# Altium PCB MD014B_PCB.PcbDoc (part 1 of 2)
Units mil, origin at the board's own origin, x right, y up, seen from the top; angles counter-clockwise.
Board outline 2500 x 1545 mil, 2 copper layers (Top Layer, Bottom Layer), stack 64.8 mil thick; 63 components, 34 nets, 144 pads, 182 vias.
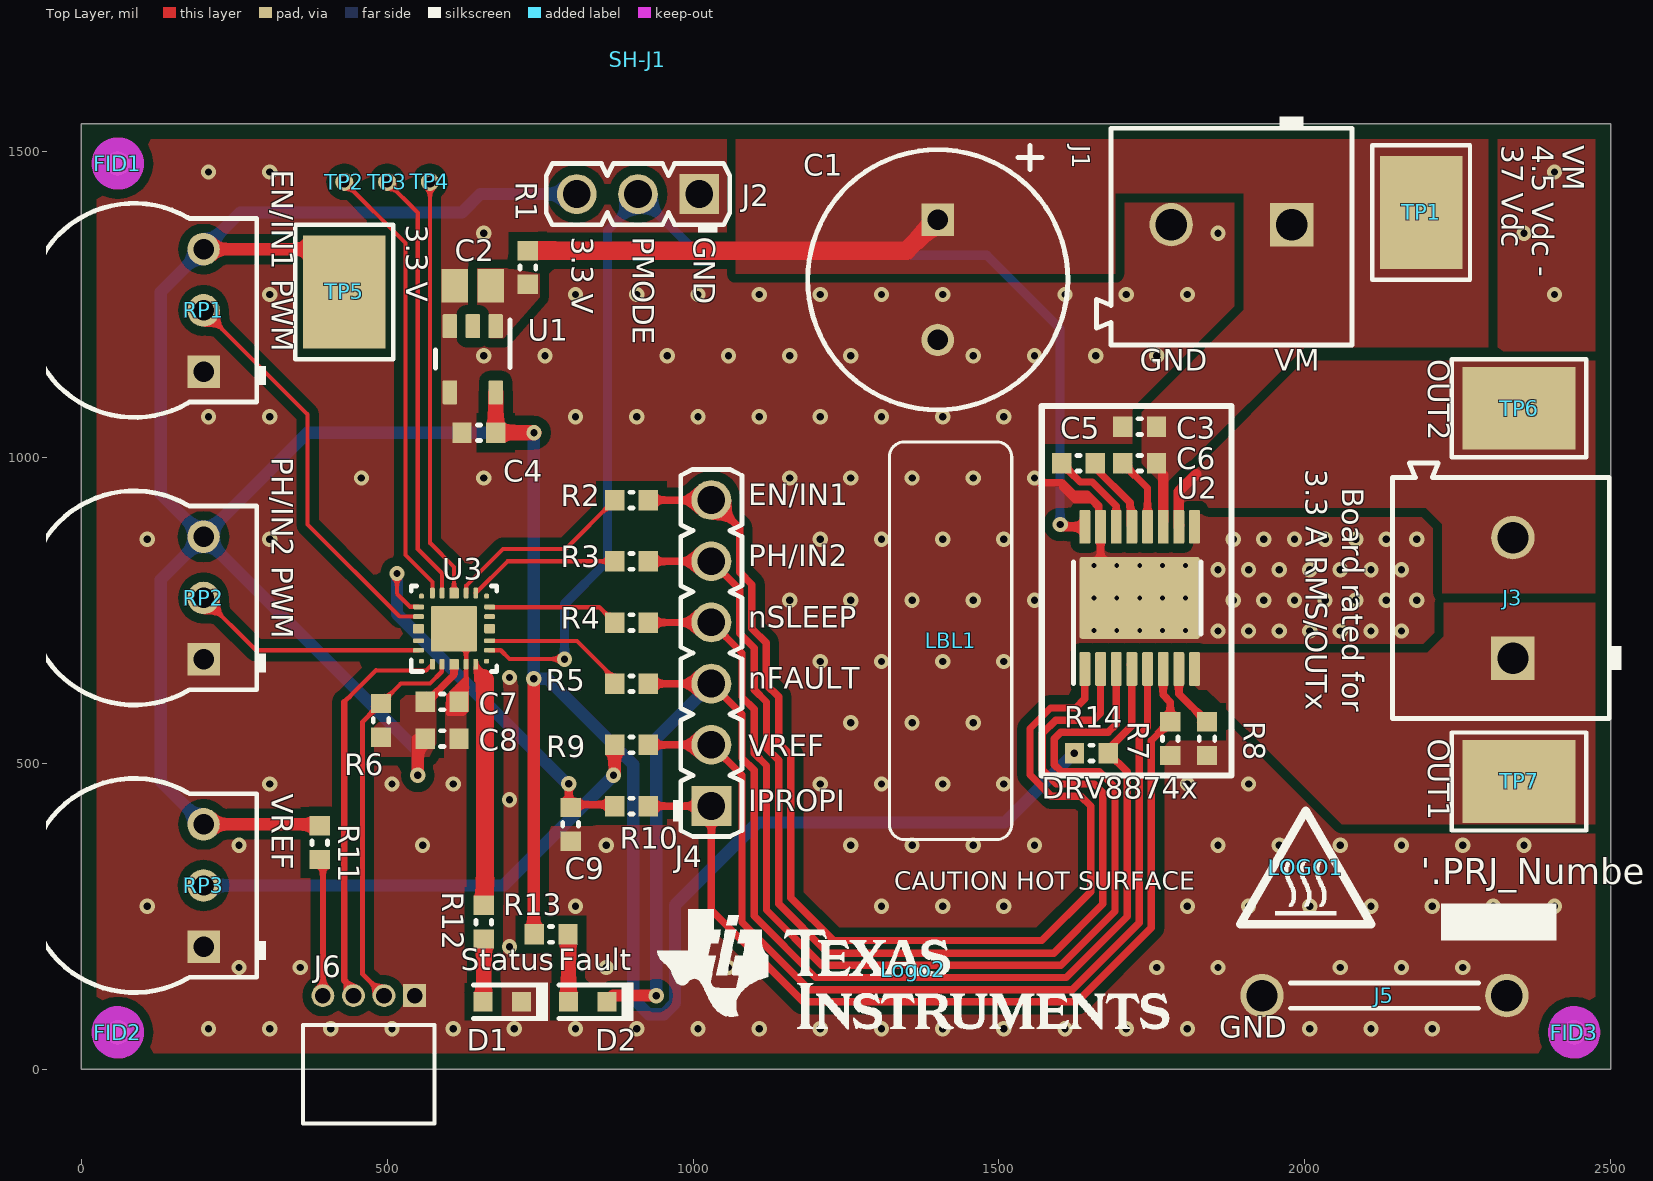
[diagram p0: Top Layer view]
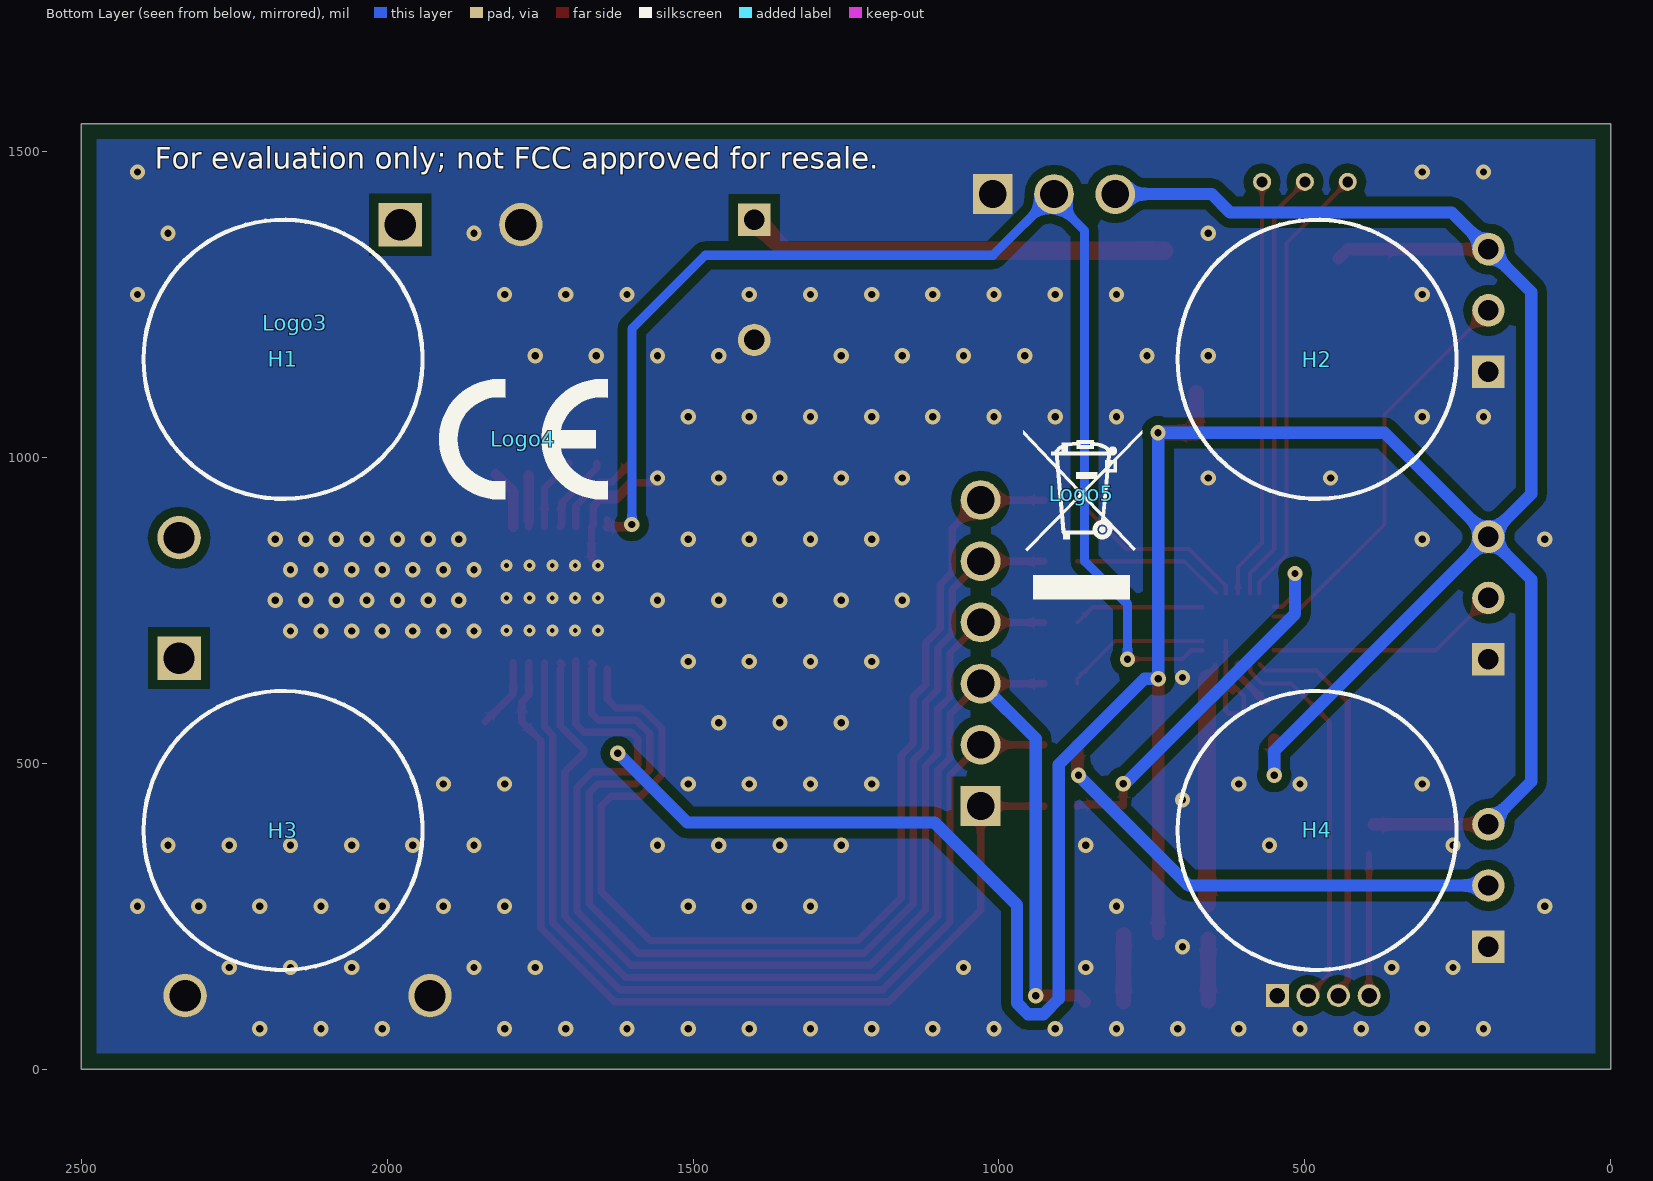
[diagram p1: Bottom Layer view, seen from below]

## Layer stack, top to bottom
Top Solder: solder mask 0.4, Solder Resist, Dk 3.5
Top Layer: signal copper 2.8
Dielectric1: core 59.2, FR-4, Dk 4.8
Bottom Layer: signal copper 2.8
Bottom Solder: solder mask 0.4, Solder Resist, Dk 3.5

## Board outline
0,0 2500,0 2500,1545 0,1545

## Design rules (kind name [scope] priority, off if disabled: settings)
AcuteAngle [All] p1: minimum=4.50000000000000E+0001 checktracksonly=FALSE
AssemblyTestPointUsage [All] p1: valid=2
BoardOutlineClearance BoardOutlineClearance_MountingHoles [OnCopper and InComponentClass('Mounting Holes')] p1: gap=40 ignorepadtopadclearanceinfootprint=FALSE
BoardOutlineClearance BoardOutlineClearance_Poly [OnCopper and IsPoly] p2: gap=25 ignorepadtopadclearanceinfootprint=FALSE
BoardOutlineClearance [OnCopper and Not InComponentClass('Logo') and not InComponentClass('FiducialMark') and not InRegion(1000,500,4000,800) and not InPoly] p3: gap=50 ignorepadtopadclearanceinfootprint=FALSE
Clearance "Stitching GND" [IsStitchingVia and InNet('GND') vs (IsVia and (Not IsStitchingVia)) Or IsPad] p1: gap=15 ignorepadtopadclearanceinfootprint=FALSE
Clearance Clearance_Keepouts [((IsTrack Or IsArc) And Not InPoly) And IsFree and IsKeepOut vs ((IsTrack Or IsArc) And Not InPoly) And IsFree and IsKeepOut] p2: gap=0 ignorepadtopadclearanceinfootprint=FALSE
Clearance Clearance_Poly [InPolygon] p3: gap=15 ignorepadtopadclearanceinfootprint=FALSE except(0: Arc-Hole Track-Hole SMDPad-Hole THPad-Hole Via-Hole Fill-Hole Poly-Hole Region-Hole Text-Hole)
Clearance Clearance_FiducialMark [IsKeepOut and InComponentClass('FiducialMark') vs IsPad and InComponentClass('FiducialMark')] p4: gap=0 ignorepadtopadclearanceinfootprint=FALSE
Clearance [All] p5: gap=7.87 ignorepadtopadclearanceinfootprint=FALSE except(0: Arc-Hole Track-Hole SMDPad-Hole THPad-Hole Via-Hole Fill-Hole Poly-Hole Region-Hole Text-Hole)
ComponentClearance ComponentClearance_MountingHoles_FiducialMarks [InComponentClass('Mounting Holes') vs InComponentClass('FiducialMark')] p1: gap=50 collisioncheckmode=3 verticalgap=10 showdistances=FALSE
ComponentClearance ComponentClearance_Shunt [InComponentClass('Header') vs InComponentClass('Shunt')] p2: gap=0 collisioncheckmode=3 verticalgap=0 showdistances=FALSE
ComponentClearance ComponentClearance_Logo [InComponentClass('Logo')] p3: gap=50 collisioncheckmode=3 verticalgap=10 showdistances=FALSE
ComponentClearance ComponentClearance_ScrewToNut [(HasFootprint('NY PMS 440 0025 PH')) vs (HasFootprint('Keystone_1902C'))] p4: gap=5 collisioncheckmode=3 verticalgap=10 showdistances=FALSE
ComponentClearance ComponentClearance_MountingHoles [InComponentClass('Mounting Holes')] p5: gap=250 collisioncheckmode=3 verticalgap=100000 showdistances=FALSE
ComponentClearance ComponentClearance_SmallPassives [HasFootprint('0201*') or HasFootprint('0402*') or HasFootprint('0508') or HasFootprint('0603*') or HasFootprint('0612') or HasFootprint('0805*') or HasFootprint('0815*') or HasFootprint('0830*') or HasFootprint('1206*') or HasFootprint('1210*') or HasFootprint('1808*') or HasFootprint('1812*') or HasFootprint('1825*') or HasFootprint('2010*') or HasFootprint('2220*') or HasFootprint('2225*') or HasFootprint('2512*') or HasFootprint('2728*') or HasFootprint('3518*') vs HasFootprint('0201*') or HasFootprint('0402*') or HasFootprint('0508') or HasFootprint('0603*') or HasFootprint('0612') or HasFootprint('0805*') or HasFootprint('0815*') or HasFootprint('0830*') or HasFootprint('1206*') or HasFootprint('1210*') or HasFootprint('1808*') or HasFootprint('1812*') or HasFootprint('1825*') or HasFootprint('2010*') or HasFootprint('2220*') or HasFootprint('2225*') or HasFootprint('2512*') or HasFootprint('2728*') or HasFootprint('3518*')] p6: gap=14.96 collisioncheckmode=3 verticalgap=10 showdistances=FALSE
ComponentClearance ComponentClearance_THtoSMT [IsThruComponent vs IsSMTComponent] p7: gap=40 collisioncheckmode=3 verticalgap=30 showdistances=FALSE
ComponentClearance ComponentClearance_THtoTH [IsThruComponent vs IsThruComponent] p8: gap=30 collisioncheckmode=3 verticalgap=30 showdistances=FALSE
ComponentClearance [All] p9: gap=30 collisioncheckmode=3 verticalgap=10 showdistances=FALSE
DiffPairsRouting [All] p1: maxlimit=100 minlimit=10 mostfreqgap=10 toplayer_minwidth=15 toplayer_maxwidth=15 toplayer_prefwidth=15 bottomlayer_minwidth=15 bottomlayer_maxwidth=15 bottomlayer_prefwidth=15 maxuncoupledlength=1000
FabricationTestPointUsage TestPointUsage [All] p1: valid=2 allowmultiple=FALSE
FabricationTestpoint Testpoint [All] p1: side=3 testpointundercomponent=TRUE minsize=40 maxsize=100 preferedsize=60 minholesize=0 maxholesize=40 preferedholesize=32 testpointgrid=1 allowsidetop=TRUE allowsidebottom=TRUE usegrid=TRUE gridtolerance=0.01
FanoutControl Fanout_LCC [IsLCC] p1: bgadir=Out bgaviamode=Centered fanoutstyle=Auto fanoutdirection=Alternating viagrid=1 // Fanout_LCC (Default Rule)
FanoutControl Fanout_BGA [IsBGA] p2: bgadir=Out bgaviamode=Centered fanoutstyle=Auto fanoutdirection=Alternating viagrid=1 // Fanout_BGA (Default Rule)
FanoutControl Fanout_Default [All] p4: bgadir=Out bgaviamode=Centered fanoutstyle=Auto fanoutdirection=Alternating viagrid=1 // Fanout_Default (Default Rule)
FanoutControl Fanout_Small [(CompPinCount < 5)] p5: bgadir=Out bgaviamode=Centered fanoutstyle=Auto fanoutdirection=OutThenIn viagrid=1 // Fanout_Small (Default Rule)
HoleSize [All] p1: absolutevalues=TRUE maxlimit=251 minlimit=7.87 maxpercent=80.000 minpercent=20.000
MinimumAnnularRing MinimumAnnularRing_ThermalPadVias [IsVia and InAnyComponent] p1: minimumring=5.91
MinimumAnnularRing [All] p2: minimumring=5
MinimumSolderMaskSliver MinimumSolderMaskSliver_Logo [InComponentClass('Logo') vs InComponentClass('Logo')] p1: minsoldermaskwidth=0.7
MinimumSolderMaskSliver [All] p2: minsoldermaskwidth=3.94
PlaneConnect [All] p1: planeconnectstyle=Direct reliefexpansion=10 reliefentries=4 reliefconductorwidth=10 reliefairgap=10
PolygonConnect [All] p1: connectstyle=Direct reliefconductorwidth=10 reliefentries=4 polygonreliefangle="90 Angle" airgapwidth=10
RoutingVias ThermalPadVias [IsVia and InAnyComponent] p1: holewidth=7.87 width=19.68 viastyle="Through Hole" minholewidth=7.87 minwidth=19.68 maxholewidth=12.99 maxwidth=23.62
RoutingVias [All] p2: holewidth=16 width=34 viastyle="Through Hole" minholewidth=7.87 minwidth=25 maxholewidth=40 maxwidth=65
SilkToBoardRegionClearance [Not ((IsComment or IsDesignator) And (Hide <> 'False')) and not InRegion(1000,500,4000,800)] p1:
SilkToSilkClearance SilkToSilkClearance_Pb-FreeLogo [(HasFootprint('Pb-Free_Overlay_Medium') OR HasFootprint('Pb-Free_Overlay_Small')) vs (HasFootprint('Pb-Free_Overlay_Medium') OR HasFootprint('Pb-Free_Overlay_Small'))] p1: silktosilkclearance=0
SilkToSilkClearance [All] p2: silktosilkclearance=4
SilkToSolderMaskClearance SilkToComponentPadClearance [(IsPad or IsFill or IsRegion) and InAnycomponent] p1: minsilkscreentomaskgap=5 clearancetoexposedcopper=TRUE
SilkToSolderMaskClearance "Silk to Solder Mask Opening" [All] p2: minsilkscreentomaskgap=4 clearancetoexposedcopper=FALSE
SolderMaskExpansion [All] p1: expansion=1.97
Width [All] p1: maxlimit=100 minlimit=6 preferedwidth=10 checkconnectedcopper=TRUE
15 further rules are at their usual default settings.

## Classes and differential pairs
component class MD014B_Hardware: !PCB1 FID1 FID2 FID3 H1 H2 H3 H4 LBL1 LOGO1 Logo2 Logo3 Logo4 Logo5 ZZ1 ZZ2 ZZ3 ZZ4 ZZ5
component class Header: J2 J4
component class MD014B_SCH: C1 C2 C3 C4 C5 C6 C7 C8 C9 D1 D2 J1 J2 J3 J4 J5 J6 R1 R2 R3 R4 R5 R6 R7 R8 R9 R10 R11 R12 R13 R14 RP1 RP2 RP3 SH-J1 Text TP1 TP2 TP3 TP4 TP5 TP6 TP7 U1 U2 U3
component class Logo: Logo2
component class FiducialMark: FID1 FID2 FID3
component class AssemblyNote: ZZ1 ZZ2 ZZ3 ZZ4 ZZ5
component class Label: LBL1

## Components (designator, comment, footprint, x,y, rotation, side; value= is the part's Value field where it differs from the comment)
C1 "UBT1H101MPD1TD" BT_1000x1250 1400,1290 r270 top value=100uF
C2 "885012207103" 0805L 640,1280 r180 top value=1uF
C3 "885012206095" 0603L 1730,1050 r180 top value=0.1uF
C4 "C0603C475K8PACTU" 0603L 650,1040 r180 top value=4.7uF
C5 "885012206091" 0603L 1630,990 r180 top value=0.022uF
C6 "885012206095" 0603L 1730,990 r180 top value=0.1uF
C7 "885012206095" 0603L 590,600 r0 top value=0.1uF
C8 "885012206026" 0603L 590,540 r0 top value=1uF
C9 "885012206095" 0603L 800,400 r270 top value=0.1uF
D1 "150060VS75000" WL-SMCW_GREEN 688.05,110 r180 top value=Green
D2 "150060RS75000" WL-SMCW_RED 828.05,110 r180 top value=Red
FID1 "Fiducial" Fiducial10-20 60,1480 r90 top
FID2 "Fiducial" Fiducial10-20 60,60 r90 top
FID3 "Fiducial" Fiducial10-20 2440,60 r90 top
H1 "SJ-5303 (CLEAR)" Bumpon_SJ5003Transparent 2170,1160 r90 bottom
H2 "SJ-5303 (CLEAR)" Bumpon_SJ5003Transparent 480,1160 r90 bottom
H3 "SJ-5303 (CLEAR)" Bumpon_SJ5003Transparent 2170,390 r90 bottom
H4 "SJ-5303 (CLEAR)" Bumpon_SJ5003Transparent 480,390 r270 bottom
J1 "CMP-0054828-1" Wurth_691101710002 1880,1380 r180 top
J2 "61300311121" WURTH_61300311121 910,1430 r180 top
J3 "CMP-0054828-1" Wurth_691101710002 2340,770 r90 top
J4 "61300611121" WURTH_61300611121 1030,680 r90 top
J5 "D3082-05" Harwin_D3082-05 2130,120 r180 top
J6 "851-43-004-20-001000" CONN_851-43-004-20-001000 470,120 r0 top
LBL1 "THT-14-423-10" Label_650x200 1420.88,700.1 r90 top
LOGO1 "CAUTION HOT SURFACE" IEC_HotSurface_Small 2001.63,330 r0 top
Logo2 "Texas Instruments" TI_Stacked_Overlay_Small 1360,163.02 r0 top
Logo3 "FCC disclaimer" FCC_disclaimer 2150,1220 r180 bottom
Logo4 "CE Mark" CE_Mark_5mm 1777.24,1029.33 r180 bottom
Logo5 "WEEE logo" WEEE_Minimum 865,940 r180 bottom
R1 "ERJ-3GEY0R00V" 0603L 730,1310 r270 top value=0
R2 "ERJ-3GEY0R00V" 0603L 899.45,929.78 r180 top value=0
R3 "ERJ-3GEY0R00V" 0603L 899.45,829.78 r180 top value=0
R4 "ERJ-3GEY0R00V" 0603L 899.45,729.78 r180 top value=0
R5 "ERJ-3GEY0R00V" 0603L 899.45,629.78 r180 top value=0
R6 "CRCW060347K0JNEA" 0603L 490,570 r90 top value=47k
R7 "CRCW06031K50JNEA" 0603L 1780,540 r90 top value=1.5k
R8 "ERJ-3GEY0R00V" 0603L 1840,540 r90 top value=0
R9 "ERJ-3GEY0R00V" 0603L 899.45,529.78 r180 top value=0
R10 "ERJ-3GEY0R00V" 0603L 899.45,429.78 r180 top value=0
R11 "ERJ-3GEY0R00V" 0603L 390,370 r270 top value=0
R12 "CRCW0603330RJNEA" 0603L 658.05,240 r90 top value=330
R13 "CRCW0603330RJNEA" 0603L 768.05,220 r180 top value=330
R14 "ERA-3ARW103V" 0603L 1651.16,516.34 r0 top value=10.0k
RP1 "3352T-1-503LF" Bourns_3352T 200,1240 r90 top value=50k
RP2 "3352T-1-503LF" Bourns_3352T 200,770 r90 top value=50k
RP3 "3352T-1-503LF" Bourns_3352T 200,300 r90 top value=50k
SH-J1 "60900213421" Wurth_60900213421 910,1650 r180 top
TP1 "5016" Testpoint_Keystone_Compact 2190,1400 r270 top
TP2 "TP_H0.45P0.75" TP_H045P075 430,1450 r90 top
TP3 "TP_H0.45P0.75" TP_H045P075 500,1450 r90 top
TP4 "TP_H0.45P0.75" TP_H045P075 570,1450 r90 top
TP5 "5015" Testpoint_Keystone_Compact 430,1270 r90 top
TP6 "5016" Testpoint_Keystone_Compact 2350,1080 r0 top
TP7 "5016" Testpoint_Keystone_Compact 2350,470 r180 top
U1 "TPS7B6933DBVR" DBV0005A_N 640,1160 r270 top
U2 "DRV8874PWPR" PWP0016J_N 1730,770 r90 top
U3 "MSP430FR2100IRLLR" RLL0024A 609.45,719.78 r90 top
ZZ1 "This Assembly Note is for PCB labels only" AssemblyNoteLabel 165,2392.5 r0 top
ZZ2 "These assemblies are ESD sensitive, ESD precautions shall be observed." AssemblyNote 165,2283.61 r0 top
ZZ3 "These assemblies must be clean and free from flux and all contaminants. Use of no clean flux is not acceptable." AssemblyNote 165,2195.06 r0 top
ZZ4 "These assemblies must comply with workmanship standards IPC-A-610 Class 2, unless otherwise specified." AssemblyNote 165,2106.5 r0 top
ZZ5 "Board material shall meet UL MOT of 130C" AssemblyNote 160,2010 r0 top

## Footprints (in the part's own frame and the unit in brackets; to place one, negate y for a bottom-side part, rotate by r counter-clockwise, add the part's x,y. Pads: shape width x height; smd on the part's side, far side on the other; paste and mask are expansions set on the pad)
0603L [mm] "0603 from SM-752 data"
  rect 0.8x0.85 smd: 1(-0.7,0) 2(0.7,0)
  silkscreen extent -0.07,-0.33 0.07,0.33, body extent -0.87,-0.47 0.87,0.47, height 1
0805L [mm] "0805 from SM-752 data"
  rect 1.1x1.4 smd: 1(-0.75,0) 2(0.75,0)
  body extent -1.1,-0.72 1.1,0.72, height 1.45
AssemblyNote [mil] "Assembly Note"
AssemblyNoteLabel [mil] "Assembly Note for PCB Labels"
Bourns_3352T [mm] "TH, 3-Leads, Body 9.53x8.89mm, Pitch 2.54mm"
  rect 1.35x1.35 hole 0.85: 1(-2.54,0)
  round 1.35 hole 0.85: 2(0,0) 3(2.54,0)
  silkscreen extent -4.44,-2.6 4.44,7.31, body extent -4.44,-2.21 4.45,7.32, height 3.81
BT_1000x1250 [mm] "Nichicon"
  rect 1.35x1.35 hole 0.85 paste+0: 1(-2.5,0)
  round 1.35 hole 0.85 paste+0: 2(2.5,0)
  silkscreen extent -5.58,-5.4 5.4,5.4, body extent -5.36,-5.39 5.39,5.39, height 14.51
Bumpon_SJ5003Transparent [mil] "3M Hemispherical Bumpon transparent"
  round 1 on Mech4: 0(0,0)
  silkscreen extent -228,-228 228,228, body extent -219,-219 219,219, height 197
CE_Mark_5mm [mil] "Minimum text height for CE Mark"
  silkscreen extent -138,-98 138,98
CONN_851-43-004-20-001000 [mm] "MILL-MAX"
  rect 0.95x0.95 hole 0.65: 1(1.905,0)
  round 0.95 hole 0.65: 2(0.635,0) 3(-0.635,0) 4(-1.905,0)
  silkscreen extent -2.73,-5.31 2.73,-1.22, body extent -2.73,-5.31 2.73,0.23, height 2.23
DBV0005A_N [mm] "SOT23, 5-Leads, Body 2.9x1.6mm, Pitch 0.95mm, Lead Span 2.8mm, IPC Medium Density"
  rrect17% 1x0.6 smd: 1(-1.375,0.95) 2(-1.375,0) 3(-1.375,-0.95) 4(1.375,-0.95) 5(1.375,0.95)
  silkscreen extent -1.63,-1.55 0.38,1.55, body extent -1.42,-1.46 1.42,1.46, height 1.09
FCC_disclaimer [mil]
Fiducial10-20 [mm]
  round 1 smd mask+0.5: 1(0,0)
  Top Layer keep-out circle w1.178: c0,0 r0.5
Harwin_D3082-05 [mm] "Shorting Plug, 10.16mm spacing, TH"
  round 1.8 hole 1.3: 1(-5.08,0) 2(5.08,0)
  silkscreen extent -3.9,-0.53 3.9,0.53, body extent -5.6,-0.52 5.61,0.52, height 6.63
IEC_HotSurface_Small [mil]
  silkscreen extent -107,-93 107,92
Label_650x200 [mil] "Thermal Transfer Label"
  round 1 on Mech13: 0(0,0)
  silkscreen extent -325,-100 325,100, body extent -325,-100 325,100, height 1
PWP0016J_N [mm] "TSOP, 16-Leads, Body 5x4.4mm, Pitch 0.65mm, Exposed Pad, IPC Medium Density"
  rrect22% 1.4x0.45 smd: 1(-2.95,2.275) 2(-2.95,1.625) 3(-2.95,0.975) 4(-2.95,0.325) 5(-2.95,-0.325) 6(-2.95,-0.975) 7(-2.95,-1.625) 8(-2.95,-2.275) 9(2.95,-2.275) 10(2.95,-1.625) 11(2.95,-0.975) 12(2.95,-0.325) 13(2.95,0.325) 14(2.95,0.975) 15(2.95,1.625) 16(2.95,2.275)
  rrect6% 3.4x5 smd paste-1.7 mask-1.7: 17(0,0)
  rrect4% 2.46x3.55 on Top Paste: 17(0,0)
  rrect4% 2.46x3.55 on Top Solder: 17(0,0)
  silkscreen extent -3.55,-2.55 1.5,2.75, body extent -3.2,-2.5 3.2,2.5, height 1.13
RLL0024A [mm] "QFN, 24-Leads, Body 3x3mm"
  rrect50% 0.45x0.2 smd: 1(-1.475,0.9) 2(-1.475,0.5) 4(-1.475,-0.5) 5(-1.475,-0.9) 13(1.475,-0.9) 14(1.475,-0.5) 16(1.475,0.5) 17(1.475,0.9)
  rrect25% 0.45x0.4 smd: 3(-1.475,0) 15(1.475,0)
  rrect50% 0.2x0.2 smd: 6(-1.35,-1.35) 12(1.35,-1.35) 18(1.35,1.35) 24(-1.35,1.35)
  rrect50% 0.2x0.45 smd: 7(-0.9,-1.475) 8(-0.5,-1.475) 10(0.5,-1.475) 11(0.9,-1.475) 19(0.9,1.475) 20(0.5,1.475) 22(-0.5,1.475) 23(-0.9,1.475)
  rrect25% 0.4x0.45 smd: 9(0,-1.475) 21(0,1.475)
  rrect5% 1.9x1.9 smd paste-1.9: 25(0,0)
  rrect6% 1.71x1.71 on Top Paste: ""(0,0)
  silkscreen extent -1.78,-1.78 1.78,1.78, body extent -1.58,-1.58 1.58,1.58, height 1.01
Testpoint_Keystone_Compact [mil] "Compact SMT test point"
  rect 185x135 smd: 1(0,0)
  silkscreen extent -110,-80 110,80, body extent -75,-56 75,56, height 91
TI_Stacked_Overlay_Small [mil]
  silkscreen extent -418,-98 418,98
TP_H045P075 [mm] "TP_H0.45P0.75"
  round 0.75 hole 0.45: 1(0,0)
WEEE_Minimum [mil] "WEEElie bin"
  silkscreen extent -95,-172 99,104
WL-SMCW_GREEN [mm] "WURTH"
  rect 0.8x0.8 smd: 1(-0.8,0) 2(0.8,0)
  silkscreen extent -1.9,-0.8 1.2,0.8, body extent -0.85,-0.45 0.85,0.45, height 0.8
WL-SMCW_RED [mm] "WURTH"
  rect 0.8x0.8 smd: 1(-0.8,0) 2(0.8,0)
  silkscreen extent -1.9,-0.8 1.2,0.8, body extent -0.85,-0.45 0.85,0.45, height 0.8
Wurth_60900213421 [mil] "Shunt, 2.54mm, Black"
  round 1 on Mech3: 0(0,0)
  body extent -98,-48 98,48, height 236
WURTH_61300311121 [mm] "Header, 2.54mm, 3x1, TH"
  rect 1.65x1.65 hole 1.15: 1(-2.54,0)
  round 1.65 hole 1.15: 2(0,0) 3(2.54,0)
  silkscreen extent -3.81,-1.27 3.81,1.6, body extent -3.81,-1.27 3.81,1.27, height 8.54
WURTH_61300611121 [mm] "Header, 2.54mm, 6x1, TH"
  rect 1.65x1.65 hole 1.15: 1(-6.35,0)
  round 1.65 hole 1.15: 2(-3.81,0) 3(-1.27,0) 4(1.27,0) 5(3.81,0) 6(6.35,0)
  silkscreen extent -7.62,-1.27 7.62,1.6, body extent -7.62,-1.27 7.62,1.27, height 8.54
Wurth_691101710002 [mm] "Terminal Block, 5 mm, 2x1, TH"
  rect 1.8x1.8 hole 1.3: 1(-2.5,0)
  round 1.8 hole 1.3: 2(2.5,0)
  silkscreen extent -5,-4.5 5.6,5, body extent -5.6,-4 5.6,5, height 12.5

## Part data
C1: library part CMP-0009918-2, "CAP, AL, 100 uF, 50 V, +/- 20%, TH", Cap_Case=10x12.5mm, Manufacturer=Nichicon, Supplier Part Number 1=493-4508-1-ND, Tolerance_%=20%, Value1=Unknown, Value2=50V, ValueDisplayed=100uF
C2: library part CMP-0007696-2, "CAP, CERM, 1 uF, 50 V, +/- 10%, X7R, 0805", Cap_Case=0805, Manufacturer="Wurth Elektronik", Supplier Part Number 1=710-885012207103, TempCo=X7R, Tolerance_%=10%, Value1=Unknown, Value2=50V, ValueDisplayed=1uF
C3 C6 C7 C9: library part CMP-0006837-4, "CAP, CERM, 0.1 uF, 50 V, +/- 10%, X7R, 0603", Cap_Case=0603, Manufacturer="Wurth Elektronik", TempCo=X7R, Tolerance_%=10%, Value1=Unknown, Value2=50V, ValueDisplayed=0.1uF
C4: library part CMP-0006949-5, "CAP, CERM, 4.7 uF, 10 V, +/- 10%, X5R, 0603", Cap_Case=0603, Manufacturer=Kemet, Supplier Part Number 1=399-5503-1-ND, TempCo=X5R, Tolerance_%=10%, Value1="0.006 ohm", Value2=10V, ValueDisplayed=4.7uF
C5: library part CMP-0006836-4, "CAP, CERM, 0.022 uF, 50 V, +/- 10%, X7R, 0603", Cap_Case=0603, Manufacturer="Wurth Elektronik", TempCo=X7R, Tolerance_%=10%, Value1=Unknown, Value2=50V, ValueDisplayed=0.022uF
C8: library part CMP-0064932-4, "CAP, CERM, 1 uF, 10 V,+/- 10%, X7R, 0603", Cap_Case=0603, Manufacturer="Wurth Elektronik", Supplier Part Number 1=732-7945-1-ND, TempCo=X7R, Tolerance_%=10%, Value1=Unknown, Value2=10V, ValueDisplayed=1uF
D1: library part CMP-0002894-1, "LED, Green, SMD", Color=green, Manufacturer="Wurth Elektronik", Supplier Part Number 1=732-4980-1-ND, Value1=W, Value2=2V
D2: library part CMP-0002947-2, "LED, Red, SMD", Color=Red, Manufacturer="Wurth Elektronik", Power_TotalModule=72mW, Supplier Part Number 1=732-4978-1-ND, Value1=0.072W, Value2=2V
FID1 FID2 FID3: library part CMP-0077181-1, "Fiducial mark.  There is nothing to buy or mount.", Manufacturer=N/A
H1 H2 H3 H4: library part CMP-0003620-1, "Bumpon, Hemisphere, 0.44 X 0.20, Clear", Manufacturer=3M, Supplier Part Number 1=SJ5303-7-ND
J1 J3: "Terminal Block, 5 mm, 2x1, Tin, TH", Manufacturer="Wurth Elektronik", PartNumber="691 101 710 002", Supplier Part Number 1=732-2026-ND
J2: library part CMP-0054796-1, "Header, 2.54 mm, 3x1, Gold, TH", Manufacturer="Wurth Elektronik", Supplier Part Number 1=732-5316-ND
J4: library part CMP-0054801-1, "Header, 2.54 mm, 6x1, Gold, TH", Manufacturer="Wurth Elektronik", Supplier Part Number 1=732-5319-ND
J5: library part CMP-0075110-1, "1mm Uninsulated Shorting Plug, 10.16mm spacing, TH", Manufacturer=Harwin, Supplier Part Number 1=952-1873-ND
J6: library part CMP-0055060-1, "SOCKET .050\" GRID SIP 4 POS R/A, TH", Manufacturer=Mill-Max, Supplier Part Number 1=ED90474-ND
LBL1: library part CMP-0003625-1, "Thermal Transfer Printable Labels, 0.650\" W x 0.200\" H - 10,000 per roll", Manufacturer=Brady, Supplier Part Number 1=97C5133
LOGO1: library part CMP-0074837-1, "IEC 61010-1 Hot Surface Warning"
Logo2: library part CMP-0074838-1, "Texas Instrument Corporate Signature"
Logo3: library part CMP-0074847-1, "FCC_disclaimer"
Logo4: library part CMP-0074844-1
Logo5: library part CMP-0074769-1
R1 R2 R3 R4 R5 R8 R9 R10 R11: library part CMP-0025874-3, "RES, 0, 5%, 0.1 W, 0603", Manufacturer=Panasonic, Power_W=100mW, Supplier Part Number 1=P0.0GCT-ND, TempCo="600 ppm/C", Tolerance_%=5%, Value2=0.1W, Value_Code=0000, ValueDisplayed=0
R6: library part CMP-0025814-4, "RES, 47 k, 5%, 0.1 W, AEC-Q200 Grade 0, 0603", Manufacturer=Vishay-Dale, Power_W=100mW, Supplier Part Number 1=541-47KGCT-ND, TempCo="200 ppm/C", Tolerance_%=5%, Value2=0.1W, Value_Code=47k0, ValueDisplayed=47k
R7: library part CMP-0025733-4, "RES, 1.5 k, 5%, 0.1 W, AEC-Q200 Grade 0, 0603", Manufacturer=Vishay-Dale, Power_W=100mW, Supplier Part Number 1=541-1.5KGCT-ND, TempCo="200 ppm/C", Tolerance_%=5%, Value2=0.1W, Value_Code=1k50, ValueDisplayed=1.5k
R12 R13: library part CMP-0025785-4, "RES, 330, 5%, 0.1 W, AEC-Q200 Grade 0, 0603", Manufacturer=Vishay-Dale, Power_W=100mW, Supplier Part Number 1=541-330GCT-ND, TempCo="200 ppm/C", Tolerance_%=5%, Value2=0.1W, Value_Code=330R, ValueDisplayed=330
R14: library part CMP-0086251-1, "RES, 10.0 k, 0.05%, 0.1 W, AEC-Q200 Grade 0, 0603", Manufacturer=Panasonic, Power_W=100mW, TempCo="10 ppm/C", Tolerance_%=0.05%, Value2=0.1W, Value_Code=10k0, ValueDisplayed=10.0k
RP1 RP2 RP3: library part CMP-0001777-2, "Trimming Potentiometer, 50K, 0.5W, TH", Manufacturer=Bourns, Supplier Part Number 1=3352T-503LF-ND
SH-J1: library part CMP-0003761-1, "Shunt, 2.54mm, Gold, Black", Manufacturer="Wurth Elektronik", Supplier Part Number 1=732-2678-ND
TP1 TP6 TP7: library part CMP-0055153-1, "Test Point, Compact, SMT", Manufacturer=Keystone, Supplier Part Number 1=36-5016TR-ND
TP2 TP3 TP4: library part CMP-0003719-1, "Testpoint", Manufacturer="Texas Instruments"
TP5: library part CMP-0055153-1, "Test Point, Compact, SMT", Manufacturer=Keystone, PartNumber=5016, Supplier Part Number 1=36-5016TR-ND
U1: library part CMP-0077328-2, "40-V Ultralow-Iq Low-Dropout Regulator, DBV0005A (SOT-23-5)", Alternate Manufacturer="Texas Instruments"
U2: library part CMP-0081845-1, "H-Bridge Motor Drivers With Integrated Current Sense and Regulation, PWP0016J (HTSSOP-16)", Alternate Manufacturer="Texas Instruments", Alternate PartNumber=DRV8874PWP
U3: library part CMP-0080370-1, "16 MHz Ultra-Low-Power Microcontroller With 1 KB FRAM, 0.5 KB SRAM, 12 IO, 8 ch 10-bit ADC, RLL0024A (VQFN-24)", Alternate Manufacturer="Texas Instruments", Alternate PartNumber=MSP430FR2100IRLLT
ZZ1: library part CMP-0003616-3
ZZ2: library part CMP-0077236-1
ZZ3: library part CMP-0077237-1
ZZ4: library part CMP-0077238-1
ZZ5: library part CMP-0077238-1, "These assemblies must comply with workmanship standards IPC-A-610 Class 2, unless otherwise specified."

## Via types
v1: diameter 25, hole 12, Top Layer to Bottom Layer, tented both sides, 165 vias
v2: diameter 19.68, hole 7.87, Top Layer to Bottom Layer, tented both sides, 12 vias
v3: diameter 19.68, hole 7.87, Top Layer to Bottom Layer, 3 vias
v4: diameter 25/25 (per signal layer), hole 12, Top Layer to Bottom Layer, tented both sides, 1 vias
v5: diameter 25, hole 12, Top Layer to Bottom Layer, 1 vias

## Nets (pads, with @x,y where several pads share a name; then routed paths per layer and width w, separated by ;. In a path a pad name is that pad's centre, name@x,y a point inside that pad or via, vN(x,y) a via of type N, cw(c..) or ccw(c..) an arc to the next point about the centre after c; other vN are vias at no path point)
CPH: C5.1 U2.13 | length 128.6
  Top Layer w12: C5.1@1657.56,990 1657.56,982.44 1714.35,925.65 1714.35,889 U2.13@1717.2,886.14
CPL: C5.2 U2.14 | length 152.2
  Top Layer w12: C5.2@1602.44,990 1633.05,959.39 1652.5,959.39 1691.61,920.28 U2.14@1691.61,886.14
EN_IN1: J4.6 R2.1 U2.1 | length 1852.7
  Top Layer w12: R2.1@927.01,929.78 J4.6@1029.78,929.78 ; J4.6@1030,930 1076.35,883.65 1076.35,811.75 1096.23,791.88 1096.23,719.98 1119.75,696.46 1119.75,628.36 1139.87,608.23 1139.87,532.55 1159.75,512.68 1159.75,478.36 1159.87,478.23 1159.87,280.13 1229.87,210.13 1570.13,210.13 1649.79,289.79 1649.79,429.87 1633.68,445.98 1585.65,445.98 1550.71,480.92 1550.71,556.56 1584.35,590.2 1625.28,590.2 1640.43,605.35 U2.1@1640.43,653.86
GND: C1.2 C2.2 C3.2 C4.2 C7.2 C8.2 C9.2 D1.1 J1.2 J2.1 J5.1 J5.2 J6.1 R7.1 R8.1 RP1.1 RP2.1 RP3.1 U1.3 U1.4 U2.9 U2.15 U2.17@1730,770 U3.4 U3.25 | length 518.3
  Top Layer w7: 629.13,650.44 U3.4@629.13,661.71 U3.25@629.13,700.1
  Top Layer w8: C7.2@617.56,616.26 627.32,626.02 627.32,636.77 600,609.44 600,581.3 624.45,581.3 630,586.85 630,640 629.13,640.87 629.13,650.44
  Top Layer w12: v1@1565.73,958.27 1603.89,958.27 ; U2.17@1666.02,833.98 U2.15@1666.02,886.14 1663.17,889 1663.17,918.31 ; 1603.89,958.27 1622.64,939.52 1644.27,939.52 1663.17,920.62 1663.17,918.31 ; 1603.89,958.27 1603.89,950.74 1624.63,930 1651.47,930 1663.17,918.31
  other v1: 208,66 308,66 408,66 508,66 608,66 708,66 808,66 908,66 1008,66 1108,66 1208,66 1308,66 1408,66 1508,66 1608,66 1708,66 1808,66 2008,66 2108,66 2208,66 258,166 358,166 858,166 1058,166 1758,166 1858,166 2058,166 2158,166 2258,166 700,200 108,266 808,266 1308,266 1408,266 1508,266 1808,266 1908,266 2008,266 2108,266 2208,266 2308,266 2408,266 258,366 558,366 858,366 1258,366 1358,366 1458,366 1558,366 1858,366 1958,366 2058,366 2158,366 2258,366 2358,366 700,440 308,466 508,466 608,466 1208,466 1308,466 1408,466 1508,466 1808,466 1908,466 1258,566 1358,566 1458,566 1208,666 1308,666 1408,666 1508,666 1858,716 1908,716 1958,716 2008,716 2058,716 2108,716 2158,716 1158,766 1258,766 1358,766 1458,766 1558,766 1883,766 1933,766 1983,766 2033,766 2083,766 2133,766 2183,766 1858,816 1908,816 1958,816 2008,816 2058,816 2108,816 2158,816 108,866 308,866 1208,866 1308,866 1408,866 1508,866 1883,866 1933,866 1983,866 2033,866 2083,866 2133,866 2183,866 458,966 658,966 1158,966 1258,966 1358,966 1458,966 1558,966 208,1066 308,1066 808,1066 908,1066 1008,1066 1108,1066 1208,1066 1308,1066 1408,1066 1508,1066 658,1166 758,1166 958,1166 1058,1166 1158,1166 1258,1166 1458,1166 1558,1166 1658,1166 1758,1166 308,1266 808,1266 908,1266 1008,1266 1108,1266 1208,1266 1308,1266 1408,1266 1608,1266 1708,1266 1808,1266 2408,1266 658,1366 1858,1366 2358,1366 208,1466 308,1466 2408,1466
  other v2: 1655.2,716.85 1692.6,716.85 1730,716.85 1767.4,716.85 1804.8,716.85 1655.2,770 1804.8,770 1655.2,823.15 1692.6,823.15 1730,823.15 1767.4,823.15 1804.8,823.15
  other v3: 1692.6,770 1730,770 1767.4,770
  other v5: 700,640
IMODE: R8.2 U2.7 | length 115.4
  Top Layer w12: U2.7@1793.98,663.86 1793.98,613.58 R8.2@1840,567.56
NetC2_1: C2.1 R1.2 U1.1
NetC6_2: C6.2 U2.12 | length 120.6
  Top Layer w12: C6.2@1702.44,990 1742.8,949.65 U2.12@1742.8,886.14
NetD1_2: D1.2 R12.1 | length 100.9
  Top Layer w25: D1.2@658.05,111.5 R12.1@658.05,212.44
NetD2_2: D2.2 R13.1 | length 110
  Top Layer w25: R13.1@796.1,220 D2.2@796.56,110
NetR9_2: R9.2 RP3.2 | length 792.5
  Top Layer w20: v1@871.89,481.89 R9.2@871.89,529.78
  Bottom Layer w20: RP3.2@200,300 690,300 v1(870,480)
NetTP2_1: TP2.1 U3.17 | length 731.8
  Top Layer w7: TP2.1@430,1450 530,1350 530,840 574.01,795.99 U3.17@574.01,777.85
NetTP3_1: TP3.1 U3.16 | length 709.3
  Top Layer w7: TP3.1@500,1450 550,1400 550,850 589.76,810.24 U3.16@589.76,777.85
NetTP4_1: TP4.1 U3.15 | length 687.8
  Top Layer w7: 570,860 TP4.1@570,1450 ; 570.5,859.5 609.45,820.55 U3.15@609.45,777.85
nFAULT: D2.1 J4.3 R5.1 R14.2 U2.4 | length 2273
  Top Layer w12: R5.1@927.01,629.78 J4.3@1029.78,629.78 ; J4.3@1030,630 1080,580 1080,508.11 1099.87,488.23 1099.87,250.13 1200.25,149.75 1609.75,149.75 1709.41,249.41 1709.41,485.65 R14.2@1678.72,516.34 1678.72,522.72 1717.2,561.21 U2.4@1717.2,653.86 ; U2.4@1714.35,661 U2.4@1717.2,663.86
  Top Layer w20: D2.1@859.55,110 869.55,120 v1(940,120)
  Bottom Layer w20: v1(940,120) 940,540 J4.3@1030,630
nFAULT_MCU: R5.2 U3.8 | length 237.8
  Top Layer w6: R5.2@871.89,629.78 R5.2@871.89,638.11
  Top Layer w7: U3.8@667.95,699.66 810.34,699.66 R5.2@871.89,638.11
